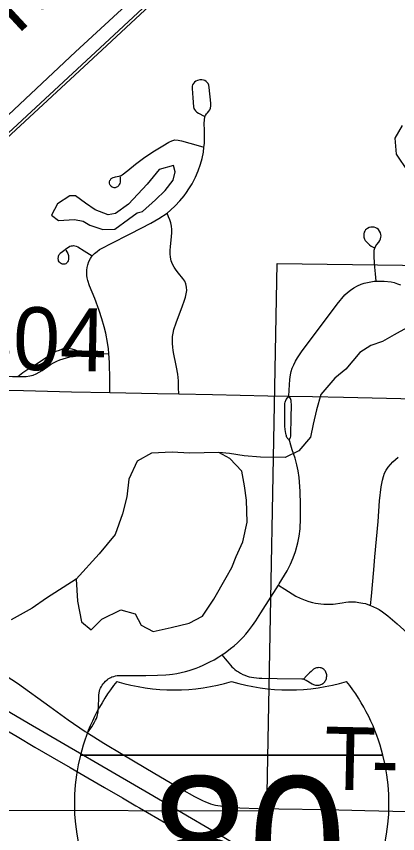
# Model space of a CAD drawing. Extents: x 0 to 34, y 0 to 22.
# Drawn here: x 5.271 to 5.615, y 18.383 to 19.121 of the extents above; entities that cross this region are included whole.
import ezdxf

# ---------------------------------------------------------------- set-up
doc = ezdxf.new("R2010")
doc.units = 0
for name, color, linetype in [('GM_X_Corporation', 7, 'Continuous'), ('GM_X_Interstate_Route', 7, 'Continuous'), ('GM_X_Interstate_Shield', 7, 'Continuous'), ('GM_X_Minor_Lake', 7, 'Continuous'), ('GM_X_Minor_River', 7, 'Continuous'), ('GM_X_Rail_Line', 7, 'Continuous'), ('GM_X_Rail_Line_Text', 7, 'Continuous'), ('GM_X_Township_Road', 7, 'Continuous'), ('GM_X_Township_Road_Text', 7, 'Continuous')]:
    doc.layers.add(name, color=color, linetype=linetype)

msp = doc.modelspace()

# ---------------------------------------------------------------- linework, layer by layer
at = {"layer": 'GM_X_Corporation'}
for points in [[(5.75551, 18.89463), (5.99643, 18.88937), (6.50454, 18.87812), (6.49696, 17.87536), (5.48857, 17.88606), (5.49728, 18.40367), (5.50661, 18.89778)], [(5.24691, 18.40433), (5.49728, 18.40367), (5.48857, 17.88606), (4.98239, 17.89994), (4.99301, 18.41185)]]:
    msp.add_lwpolyline(points, close=True, dxfattribs=at)
at = {"layer": 'GM_X_Interstate_Route'}
for points in [[(5.24813, 18.50277), (5.28214, 18.48285), (5.39066, 18.41966), (5.45017, 18.38473), (5.50003, 18.35547)], [(5.25889, 18.47839), (5.27179, 18.47089), (5.28783, 18.46137), (5.30341, 18.45231), (5.31951, 18.44289), (5.33565, 18.43355), (5.35068, 18.42477), (5.36684, 18.41547), (5.37894, 18.40839)], [(5.37894, 18.40839), (5.3824, 18.40637), (5.40605, 18.39261), (5.43285, 18.37685), (5.4457, 18.36926), (5.45911, 18.36142), (5.47517, 18.35192), (5.4902, 18.34316), (5.54771, 18.3097), (5.57406, 18.29442), (5.62344, 18.26555), (5.65628, 18.24658), (5.67238, 18.23714), (5.69219, 18.22544), (5.74567, 18.19374), (5.75986, 18.18544), (5.76924, 18.17995), (5.77465, 18.17679), (5.77902, 18.17422)]]:
    msp.add_lwpolyline(points, dxfattribs=at)
at = {"layer": 'GM_X_Interstate_Shield'}
for p, q in [((5.32884, 18.45407), (5.60209, 18.45407)), ((5.60209, 18.45407), (5.32884, 18.45407)), ((5.60209, 18.45407), (5.32884, 18.45407))]:
    msp.add_line(p, q, dxfattribs=at)
for centre, start, end in [((5.50098, 18.41053), 141.66896, 165.80665), ((5.41358, 18.69046), 253.00908, 286.99093), ((5.51735, 18.69046), 253.00908, 286.99093), ((5.42995, 18.41053), 14.19335, 38.33104), ((5.50098, 18.41053), 165.80665, 258.46304), ((5.42995, 18.41053), 281.53696, 14.19335)]:
    msp.add_arc(centre, 0.17756, start, end, dxfattribs=at)
at = {"layer": 'GM_X_Minor_Lake'}
for p, q in [((5.38029, 18.94346), (5.38484, 18.94492)), ((5.46064, 18.61452), (5.46567, 18.62357))]:
    msp.add_line(p, q, dxfattribs=at)
for points in [[(5.61932, 19.02244), (5.61275, 19.01113), (5.61407, 18.99669), (5.62444, 18.981)], [(5.38484, 18.94492), (5.39669, 18.9554), (5.40548, 18.96364), (5.41278, 18.97303), (5.41439, 18.9806), (5.41296, 18.98631), (5.40006, 18.98268), (5.38931, 18.96953), (5.37246, 18.95153), (5.36064, 18.94294), (5.35382, 18.94189), (5.34217, 18.94622), (5.33356, 18.9524), (5.32458, 18.95896), (5.31929, 18.95903), (5.30824, 18.95157), (5.30282, 18.94139), (5.30918, 18.93676), (5.32355, 18.93772), (5.33146, 18.9361), (5.33746, 18.93261), (5.34912, 18.92867), (5.36008, 18.92891), (5.37228, 18.93787), (5.38029, 18.94346)], [(5.46567, 18.62357), (5.46958, 18.63339), (5.47541, 18.6466), (5.47942, 18.66439), (5.47892, 18.68413), (5.4772, 18.69706), (5.47473, 18.71037), (5.46392, 18.7219), (5.45379, 18.72734), (5.42734, 18.72653), (5.41186, 18.72748), (5.39296, 18.72658), (5.38003, 18.71953), (5.37264, 18.70331), (5.37092, 18.68739), (5.36694, 18.67187), (5.36028, 18.65336), (5.34569, 18.63571), (5.325, 18.61281), (5.32625, 18.59306), (5.32979, 18.57442), (5.33876, 18.56709), (5.34833, 18.57684), (5.36544, 18.58536), (5.37824, 18.58178), (5.38377, 18.57146), (5.39465, 18.56563), (5.41094, 18.56922), (5.42724, 18.57319), (5.43903, 18.5795), (5.44943, 18.59493), (5.46064, 18.61452)]]:
    msp.add_lwpolyline(points, dxfattribs=at)
at = {"layer": 'GM_X_Minor_River'}
for points in [[(5.62374, 18.83982), (5.61233, 18.83352), (5.60167, 18.82758), (5.59105, 18.82391), (5.58114, 18.81759), (5.56848, 18.80256), (5.55855, 18.79434), (5.5459, 18.7797), (5.54194, 18.7657), (5.53912, 18.75283), (5.53671, 18.7411), (5.52597, 18.72871), (5.5138, 18.72279), (5.49152, 18.72307), (5.4768, 18.72439), (5.4636, 18.72645), (5.45379, 18.72734)], [(5.325, 18.61281), (5.29833, 18.59569), (5.28537, 18.58674), (5.26635, 18.57635)]]:
    msp.add_lwpolyline(points, dxfattribs=at)
at = {"layer": 'GM_X_Rail_Line'}
for points in [[(4.26344, 18.0887), (4.5545, 18.35746), (4.76549, 18.55341), (4.91971, 18.69674), (5.34686, 19.09254), (6.00471, 19.70399), (6.03893, 19.73535)], [(4.0369, 17.87629), (4.0405, 17.87963), (4.10582, 17.94022), (4.26502, 18.087), (4.55609, 18.35576), (4.76707, 18.55171), (4.9213, 18.69505), (5.34845, 19.09084), (6.00629, 19.70228), (6.04051, 19.73365)], [(6.02958, 19.7244), (6.02241, 19.71974), (5.97395, 19.69027), (5.5555, 19.30184), (5.32439, 19.08907), (5.10249, 18.8805), (5.04303, 18.84113), (4.98191, 18.81432), (4.92078, 18.80008), (4.84793, 18.79757), (4.78429, 18.80343)]]:
    msp.add_lwpolyline(points, dxfattribs=at)
at = {"layer": 'GM_X_Township_Road'}
for points in [[(5.44191, 19.03158), (5.44278, 19.03288), (5.44374, 19.03393), (5.44489, 19.03523), (5.44576, 19.03663), (5.44632, 19.03813), (5.44662, 19.04014), (5.44663, 19.04256), (5.44522, 19.05673), (5.44483, 19.05889), (5.4442, 19.06028), (5.44344, 19.06134), (5.44243, 19.06221), (5.44123, 19.06293), (5.43997, 19.06336), (5.43855, 19.06358), (5.43675, 19.06352), (5.43464, 19.06307), (5.4331, 19.06242), (5.43186, 19.06148), (5.43086, 19.06031), (5.43022, 19.05922), (5.42983, 19.05783), (5.42974, 19.05595), (5.43027, 19.04749), (5.43093, 19.03941), (5.43138, 19.03787), (5.43202, 19.03672), (5.43279, 19.03563), (5.43401, 19.03441), (5.43558, 19.03345), (5.44066, 19.03093)], [(5.44035, 19.00277), (5.4408, 19.00617), (5.44087, 19.01197), (5.44084, 19.01821), (5.44057, 19.02422), (5.44081, 19.02759), (5.44129, 19.03014), (5.44191, 19.03158)], [(5.36476, 18.97617), (5.36489, 18.97461), (5.36482, 18.97274), (5.36469, 18.97133), (5.3644, 18.97009), (5.364, 18.96914), (5.36348, 18.96832), (5.36289, 18.96757), (5.36224, 18.96701), (5.36159, 18.96665), (5.36093, 18.96636), (5.36018, 18.96623), (5.35929, 18.96623), (5.35835, 18.96642), (5.3576, 18.96672), (5.35675, 18.96737), (5.35622, 18.96793), (5.35567, 18.96858), (5.35534, 18.9693), (5.35521, 18.97032), (5.35527, 18.97159), (5.35553, 18.97267), (5.35596, 18.97352), (5.35677, 18.97454), (5.35779, 18.97526), (5.35857, 18.97562), (5.35959, 18.97594), (5.36064, 18.97618), (5.36204, 18.97642), (5.3636, 18.97669), (5.36489, 18.97706), (5.36577, 18.97742), (5.36673, 18.97798), (5.37159, 18.98194), (5.37873, 18.98764), (5.38573, 18.99302), (5.39068, 18.99634), (5.39586, 18.99949), (5.40339, 19.00419), (5.40879, 19.00732), (5.41146, 19.00866), (5.41423, 19.00936), (5.41716, 19.0093), (5.42013, 19.00872), (5.43515, 19.00434), (5.44035, 19.00277)], [(5.40714, 18.94321), (5.4102, 18.94594), (5.4144, 18.94991), (5.41882, 18.95445), (5.42244, 18.95887), (5.42482, 18.96182), (5.42687, 18.96511), (5.4297, 18.96976), (5.43276, 18.97566), (5.43514, 18.98156), (5.43729, 18.98746), (5.43887, 18.99256), (5.44001, 18.99824), (5.44035, 19.00277)], [(5.3396, 18.90481), (5.3417, 18.90688), (5.34405, 18.90883), (5.34623, 18.91036), (5.34961, 18.9124), (5.35532, 18.91529), (5.37437, 18.92505), (5.39262, 18.93425), (5.39977, 18.93845), (5.40714, 18.94321)], [(5.41765, 18.78009), (5.41749, 18.7857), (5.41732, 18.79188), (5.4171, 18.79497), (5.41674, 18.79803), (5.41574, 18.80414), (5.41516, 18.80717), (5.4133, 18.81614), (5.41275, 18.81921), (5.4123, 18.82233), (5.41201, 18.8255), (5.41196, 18.8287), (5.41218, 18.83189), (5.41266, 18.83505), (5.41338, 18.83815), (5.41522, 18.84419), (5.41735, 18.8501), (5.42076, 18.8588), (5.42284, 18.86466), (5.42373, 18.86761), (5.42446, 18.87058), (5.42491, 18.87355), (5.42484, 18.87646), (5.42421, 18.87936), (5.42305, 18.88201), (5.42136, 18.88445), (5.41736, 18.88927), (5.41545, 18.8918), (5.41367, 18.89444), (5.41209, 18.89724), (5.41085, 18.90025), (5.41017, 18.90346), (5.40995, 18.90668), (5.40999, 18.90984), (5.41014, 18.913), (5.41114, 18.92233), (5.41135, 18.92541), (5.41136, 18.92847), (5.41114, 18.93148), (5.41056, 18.93442), (5.40959, 18.93726), (5.40841, 18.94013), (5.40714, 18.94321)], [(5.5959, 18.88195), (5.59523, 18.88846), (5.5946, 18.89454), (5.59408, 18.90369), (5.594, 18.90675), (5.59425, 18.90978), (5.59479, 18.91178), (5.59561, 18.91373), (5.59648, 18.91498), (5.59825, 18.91707), (5.59921, 18.91858), (5.59985, 18.92006), (5.60024, 18.92149), (5.60037, 18.92288), (5.60024, 18.92409), (5.59994, 18.9256), (5.59907, 18.92712), (5.59799, 18.92842), (5.59686, 18.92937), (5.5956, 18.93007), (5.59422, 18.93054), (5.59266, 18.93062), (5.59118, 18.93054), (5.58962, 18.93023), (5.58819, 18.92959), (5.58711, 18.92889), (5.58633, 18.92811), (5.58564, 18.92716), (5.58521, 18.92608), (5.58486, 18.92477), (5.58469, 18.92317), (5.58491, 18.92152), (5.58538, 18.91984), (5.58603, 18.91862), (5.58768, 18.91672), (5.58989, 18.91468), (5.59145, 18.91356), (5.59392, 18.91217)], [(5.31584, 18.90991), (5.31749, 18.90686), (5.31805, 18.90522), (5.3182, 18.90392), (5.3182, 18.90273), (5.31802, 18.90158), (5.31773, 18.90038), (5.31737, 18.89943), (5.31689, 18.89872), (5.31625, 18.89808), (5.31567, 18.89767), (5.31486, 18.89738), (5.31375, 18.89715), (5.31277, 18.89721), (5.31184, 18.89756), (5.31091, 18.89807), (5.3101, 18.89877), (5.30961, 18.89948), (5.30919, 18.90029), (5.30897, 18.90107), (5.30888, 18.90184), (5.30888, 18.90294), (5.30897, 18.90364), (5.30916, 18.90448), (5.30944, 18.90525), (5.3098, 18.90594), (5.31024, 18.90655), (5.31073, 18.90706), (5.31271, 18.90868), (5.31665, 18.9117), (5.31822, 18.91269), (5.31949, 18.91338), (5.32053, 18.91379), (5.32169, 18.9139), (5.32268, 18.91398), (5.32375, 18.91384), (5.32501, 18.91355), (5.3266, 18.91276), (5.33242, 18.90934), (5.3396, 18.90481)], [(5.35445, 18.81655), (5.35412, 18.82087), (5.35335, 18.82654), (5.35199, 18.83483), (5.35038, 18.84084), (5.34826, 18.84777), (5.34572, 18.85556), (5.34183, 18.86613), (5.33709, 18.87764), (5.33553, 18.88244), (5.33498, 18.88488), (5.33471, 18.88712), (5.33458, 18.88955), (5.33464, 18.89185), (5.33505, 18.89429), (5.33559, 18.89659), (5.3366, 18.89971), (5.33796, 18.90228), (5.3396, 18.90481)], [(5.5171, 18.7781), (5.51748, 18.78364), (5.51812, 18.79308), (5.51864, 18.79735), (5.51915, 18.80046), (5.52019, 18.80343), (5.52148, 18.80654), (5.52316, 18.80964), (5.52484, 18.81262), (5.52859, 18.81819), (5.56066, 18.86102), (5.56763, 18.86956), (5.56996, 18.87176), (5.57281, 18.8737), (5.57579, 18.87578), (5.57915, 18.87758), (5.58227, 18.87909), (5.58517, 18.87999), (5.59115, 18.88134), (5.59417, 18.88181), (5.5959, 18.88195)], [(5.5959, 18.88195), (5.59718, 18.88206), (5.6002, 18.88204), (5.60326, 18.88182), (5.60938, 18.88119), (5.61231, 18.88059), (5.61518, 18.87965), (5.61801, 18.87851)], [(5.27235, 18.79594), (5.27706, 18.79935), (5.28142, 18.8025), (5.28674, 18.80554), (5.28928, 18.80715), (5.29426, 18.81055), (5.29925, 18.81406), (5.30176, 18.81575), (5.30433, 18.81731), (5.30705, 18.81863), (5.30987, 18.81978), (5.31274, 18.82072), (5.31562, 18.82131), (5.31846, 18.82139), (5.32127, 18.82089), (5.32406, 18.81993), (5.32685, 18.81878), (5.33074, 18.81671), (5.33339, 18.8153)], [(5.27235, 18.79594), (5.27696, 18.79587), (5.28007, 18.79597), (5.28316, 18.79633), (5.28617, 18.79704), (5.28904, 18.7982), (5.29178, 18.79966), (5.29442, 18.8013), (5.29939, 18.80502), (5.30199, 18.80672), (5.30469, 18.80825), (5.30748, 18.80963), (5.31033, 18.81086), (5.31324, 18.81194), (5.31621, 18.81285), (5.31923, 18.81353), (5.32229, 18.81406), (5.33339, 18.8153)], [(5.33339, 18.8153), (5.3377, 18.81579), (5.34388, 18.81617), (5.35009, 18.81638), (5.35445, 18.81655)], [(5.35549, 18.78127), (5.35549, 18.78542), (5.35549, 18.7921), (5.35548, 18.79735), (5.35522, 18.80387), (5.35514, 18.8086), (5.35445, 18.81655)], [(5.1782, 18.78498), (5.17839, 18.78751), (5.17879, 18.7891), (5.17923, 18.79015), (5.17984, 18.79096), (5.18068, 18.79157), (5.18183, 18.792), (5.18344, 18.79223), (5.19037, 18.7921), (5.20592, 18.792), (5.2154, 18.79235), (5.21889, 18.79274), (5.22748, 18.7944), (5.2336, 18.79546), (5.23667, 18.79589), (5.24597, 18.79628), (5.26764, 18.796), (5.27235, 18.79594)], [(5.25435, 18.78352), (5.27744, 18.78309), (5.32094, 18.78197), (5.35549, 18.78127)], [(5.35549, 18.78127), (5.39859, 18.7804), (5.41765, 18.78009)], [(5.41765, 18.78009), (5.44829, 18.77959), (5.49801, 18.77847), (5.5171, 18.7781)], [(5.51748, 18.7388), (5.51673, 18.73928), (5.51624, 18.73971), (5.51574, 18.74027), (5.51538, 18.7409), (5.51509, 18.74159), (5.51485, 18.74222), (5.51454, 18.74318), (5.51425, 18.74441), (5.51375, 18.74805), (5.51354, 18.75107), (5.51336, 18.75659), (5.51346, 18.7714), (5.51365, 18.77255), (5.51396, 18.77353), (5.51428, 18.77434), (5.51472, 18.77506), (5.5171, 18.7781)], [(5.5171, 18.7781), (5.53842, 18.77769), (5.56638, 18.77715), (5.64404, 18.77543), (5.68444, 18.77428), (5.73417, 18.77356), (5.79822, 18.77219)], [(5.51748, 18.7388), (5.51813, 18.73973), (5.51857, 18.74085), (5.51876, 18.74209), (5.51896, 18.7445), (5.51927, 18.7576), (5.51936, 18.77109), (5.51933, 18.77229), (5.51924, 18.77352), (5.51909, 18.77434), (5.51889, 18.775), (5.51845, 18.77591), (5.5171, 18.7781)], [(5.5077, 18.60755), (5.50847, 18.60877), (5.51559, 18.62039), (5.51868, 18.6264), (5.52112, 18.63204), (5.52314, 18.63785), (5.52522, 18.64558), (5.52642, 18.65162), (5.52726, 18.65832), (5.52767, 18.66757), (5.52766, 18.67996), (5.52719, 18.69235), (5.52639, 18.7047), (5.52555, 18.71078), (5.52443, 18.71618), (5.52274, 18.72209), (5.5201, 18.72974), (5.51894, 18.73395), (5.51798, 18.73729), (5.51748, 18.7388)], [(5.59487, 18.63323), (5.59761, 18.66511), (5.59906, 18.68377), (5.60044, 18.69621), (5.60093, 18.69932), (5.60158, 18.70242), (5.60245, 18.7055), (5.6036, 18.70848), (5.60505, 18.71136), (5.6068, 18.71405), (5.60881, 18.71655), (5.61099, 18.71886), (5.61328, 18.72104), (5.61572, 18.72309)], [(5.59086, 18.58926), (5.59164, 18.59762), (5.59384, 18.62133), (5.59487, 18.63323)], [(5.45665, 18.54464), (5.45954, 18.54652), (5.46444, 18.55023), (5.46766, 18.55285), (5.47066, 18.55545), (5.4734, 18.55806), (5.4758, 18.56072), (5.47813, 18.56336), (5.48054, 18.56633), (5.48429, 18.57121), (5.48725, 18.57529), (5.49188, 18.5826), (5.5077, 18.60755)], [(5.5077, 18.60755), (5.51354, 18.6039), (5.52355, 18.59765), (5.52736, 18.59574), (5.53192, 18.59396), (5.53521, 18.59284), (5.53839, 18.59197), (5.54115, 18.59137), (5.54345, 18.5909), (5.54587, 18.59058), (5.54872, 18.59031), (5.55291, 18.59021), (5.55718, 18.59047), (5.56512, 18.59167), (5.56842, 18.59226), (5.57105, 18.59248), (5.57401, 18.59253), (5.5773, 18.59237), (5.58023, 18.59198), (5.58402, 18.59137), (5.58634, 18.59082), (5.58854, 18.59011), (5.59086, 18.58926)], [(5.59086, 18.58926), (5.5936, 18.5881), (5.59634, 18.58677), (5.59877, 18.58544), (5.60168, 18.58356), (5.60636, 18.57994), (5.61485, 18.57257), (5.63302, 18.5565), (5.64845, 18.54343)], [(5.33545, 18.47415), (5.33915, 18.47964), (5.34177, 18.48385), (5.34267, 18.48558), (5.34333, 18.48705), (5.34405, 18.48895), (5.34447, 18.49053), (5.34471, 18.49167), (5.3449, 18.49309), (5.34499, 18.49462), (5.34518, 18.49762), (5.34539, 18.50617), (5.34551, 18.50832), (5.3457, 18.51036), (5.34603, 18.51183), (5.34646, 18.51321), (5.34712, 18.51464), (5.34784, 18.51597), (5.34859, 18.51712), (5.34945, 18.5183), (5.35036, 18.51939), (5.35155, 18.52073), (5.35294, 18.52201), (5.35402, 18.52287), (5.35521, 18.52358), (5.35625, 18.52416), (5.35739, 18.52463), (5.35896, 18.52516), (5.36053, 18.52558), (5.3622, 18.52587), (5.36386, 18.52606), (5.36957, 18.52607), (5.388, 18.52609), (5.39853, 18.52614), (5.40592, 18.52651), (5.40926, 18.52683), (5.41203, 18.52723), (5.41607, 18.5279), (5.4199, 18.52866), (5.42367, 18.52956), (5.42704, 18.53055), (5.42987, 18.53143), (5.43347, 18.53271), (5.43654, 18.5339), (5.43972, 18.53529), (5.44287, 18.53678), (5.44582, 18.53825), (5.4496, 18.54024), (5.45387, 18.54283), (5.45665, 18.54464)], [(5.45665, 18.54464), (5.45956, 18.54112), (5.46128, 18.53904), (5.46447, 18.53517), (5.46561, 18.53387), (5.467, 18.53257), (5.46841, 18.53138), (5.46983, 18.53033), (5.47161, 18.52913), (5.47344, 18.52809), (5.47561, 18.52698), (5.47727, 18.52627), (5.47951, 18.52544), (5.4813, 18.52491), (5.48341, 18.52444), (5.48541, 18.52414), (5.48791, 18.52386), (5.49045, 18.52369), (5.49265, 18.52359), (5.50647, 18.52319), (5.52895, 18.52294), (5.52959, 18.52288), (5.53073, 18.52265), (5.53133, 18.52248), (5.53197, 18.52216), (5.53283, 18.52172), (5.53813, 18.51846), (5.53921, 18.51794), (5.54027, 18.51758), (5.54105, 18.51738), (5.54192, 18.51723), (5.5427, 18.51717), (5.54359, 18.51721), (5.54454, 18.51735), (5.54528, 18.51755), (5.54612, 18.51787), (5.5469, 18.51822), (5.54765, 18.51868), (5.54828, 18.51909), (5.54904, 18.51977), (5.54946, 18.52028), (5.55, 18.52103), (5.55037, 18.52174), (5.55065, 18.52235), (5.551, 18.52331), (5.55123, 18.52435), (5.55131, 18.52539), (5.55128, 18.5265), (5.55109, 18.52754), (5.55056, 18.52898), (5.55009, 18.52987), (5.5494, 18.53084), (5.54891, 18.53131), (5.54826, 18.53177), (5.54754, 18.53218), (5.54689, 18.53248), (5.54617, 18.53276), (5.54539, 18.53295), (5.54421, 18.53307), (5.54328, 18.53303), (5.54215, 18.53284), (5.54122, 18.53254), (5.54008, 18.532), (5.53938, 18.53156), (5.53849, 18.53082), (5.5373, 18.52971), (5.53576, 18.52824), (5.53453, 18.52706), (5.533, 18.52552), (5.53055, 18.52288)], [(5.24883, 18.53189), (5.25269, 18.53027), (5.25656, 18.52864), (5.25948, 18.52725), (5.26192, 18.52579), (5.27196, 18.51893), (5.30126, 18.49791), (5.31788, 18.48593), (5.3333, 18.4755), (5.33545, 18.47415)], [(5.33545, 18.47415), (5.35009, 18.4649), (5.36716, 18.45472), (5.39602, 18.43758), (5.42009, 18.42334), (5.43199, 18.41668), (5.43917, 18.41309), (5.44196, 18.41187), (5.44426, 18.41097), (5.44632, 18.41027), (5.44833, 18.40966), (5.45074, 18.40905), (5.45308, 18.4086), (5.46226, 18.40742), (5.47275, 18.40656), (5.48949, 18.40598), (5.50813, 18.40567), (5.55038, 18.4049), (5.574, 18.40451), (5.58581, 18.40425), (5.62371, 18.40313), (5.63373, 18.40284)]]:
    msp.add_lwpolyline(points, dxfattribs=at)

# ---------------------------------------------------------------- texts
at = {"layer": 'GM_X_Interstate_Shield'}
msp.add_text('80', height=0.118371, dxfattribs=at).set_placement((5.39272, 18.31646))
at = {"layer": 'GM_X_Rail_Line_Text'}
msp.add_text('Transportation,', height=0.0566288, rotation=42.79952, dxfattribs=at).set_placement((5.23839, 19.07265))
at = {"layer": 'GM_X_Township_Road_Text'}
for s, height, rotation, p in [('T-304', 0.056818, 358.81191, (5.15372, 18.8044)), ('T', 0.05682, 358.74609, (5.54853, 18.42308)), ('-', 0.05682, 358.74881, (5.59094, 18.42215))]:
    msp.add_text(s, height=height, rotation=rotation, dxfattribs=at).set_placement(p)

doc.saveas('drawing.dxf')
